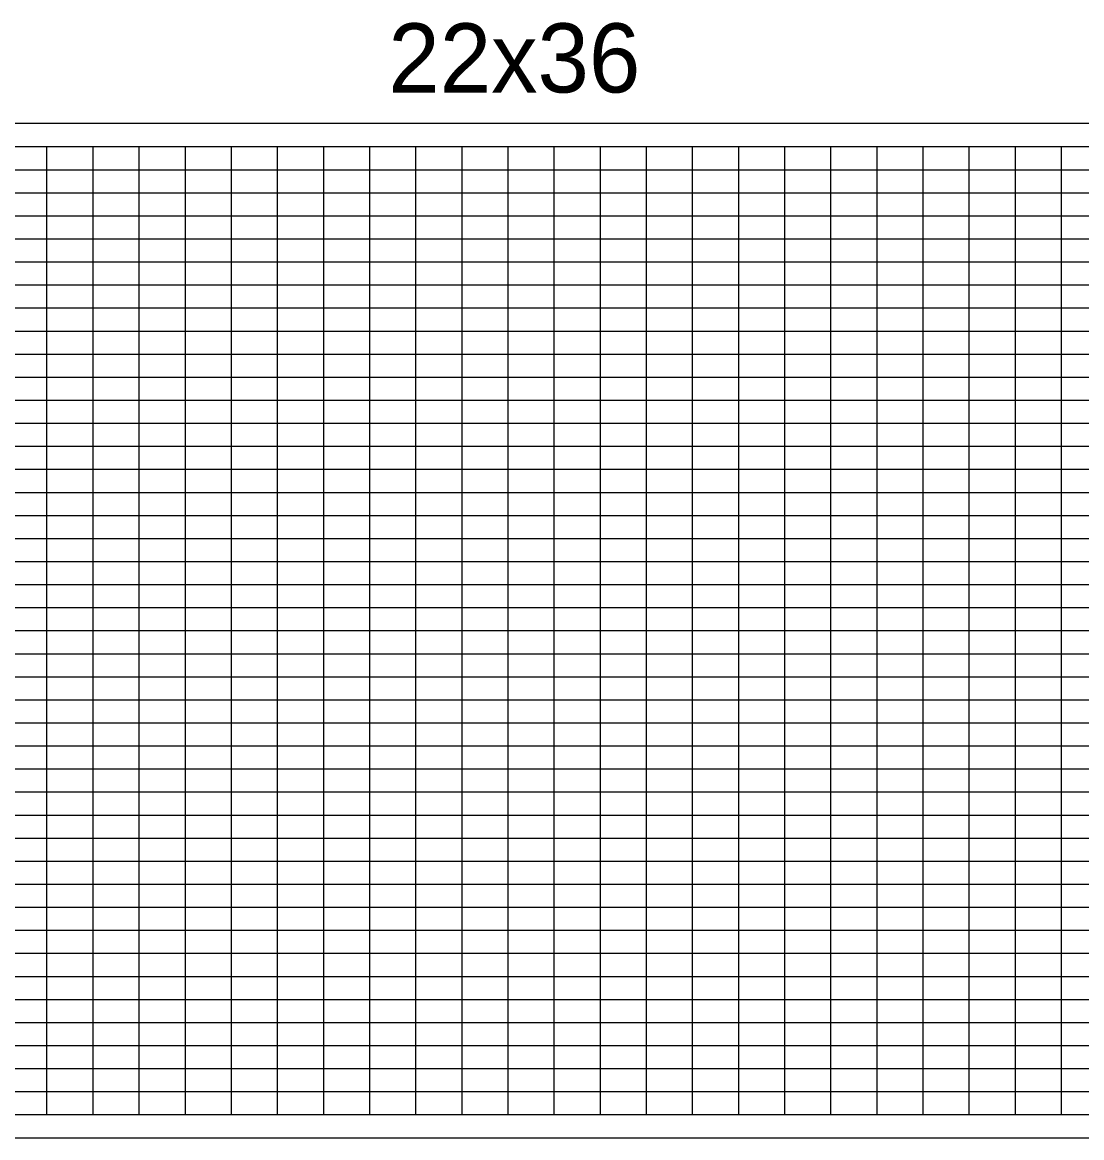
# Model space of a CAD drawing. Extents: x 1873632 to 1926512, y 813126 to 836257.
# Drawn here: x 1895536 to 1896685, y 826908 to 828118 of the extents above; entities that cross this region are included whole.
import ezdxf

# ---------------------------------------------------------------- set-up
doc = ezdxf.new("R2010")
doc.units = 0
doc.layers.add('RD_PD_WallFill', color=7, linetype='Continuous')
doc.layers.add('RD_SHT_IplotShp', color=7, linetype='Continuous')

msp = doc.modelspace()

# ---------------------------------------------------------------- linework, layer by layer
at = {"layer": 'RD_PD_WallFill'}
for p, q in [((1894363.1, 827983.1), (1899713.1, 827983.1)), ((1894363.1, 827983.1), (1896113.1, 827983.1)), ((1895563.1, 826933.1), (1895563.1, 827983.1)), ((1895563.1, 826933.1), (1895563.1, 827983.1)), ((1895613.1, 826933.1), (1895613.1, 827983.1)), ((1895613.1, 826933.1), (1895613.1, 827983.1)), ((1895663.1, 826933.1), (1895663.1, 827983.1)), ((1895663.1, 826933.1), (1895663.1, 827983.1)), ((1895713.1, 826933.1), (1895713.1, 827983.1)), ((1895713.1, 826933.1), (1895713.1, 827983.1)), ((1895763.1, 826933.1), (1895763.1, 827983.1)), ((1895763.1, 826933.1), (1895763.1, 827983.1)), ((1895813.1, 826933.1), (1895813.1, 827983.1)), ((1895813.1, 826933.1), (1895813.1, 827983.1)), ((1895863.1, 826933.1), (1895863.1, 827983.1)), ((1895863.1, 826933.1), (1895863.1, 827983.1)), ((1895913.1, 826933.1), (1895913.1, 827983.1)), ((1895913.1, 826933.1), (1895913.1, 827983.1)), ((1895963.1, 826933.1), (1895963.1, 827983.1)), ((1895963.1, 826933.1), (1895963.1, 827983.1)), ((1896013.1, 826933.1), (1896013.1, 827983.1)), ((1896013.1, 826933.1), (1896013.1, 827983.1)), ((1896063.1, 826933.1), (1896063.1, 827983.1)), ((1896063.1, 826933.1), (1896063.1, 827983.1)), ((1896113.1, 826933.1), (1896113.1, 827983.1)), ((1896113.1, 826933.1), (1896113.1, 827983.1)), ((1896163.1, 826933.1), (1896163.1, 827983.1)), ((1896163.1, 826933.1), (1896163.1, 827983.1)), ((1896213.1, 826933.1), (1896213.1, 827983.1)), ((1896213.1, 826933.1), (1896213.1, 827983.1)), ((1896263.1, 826933.1), (1896263.1, 827983.1)), ((1896263.1, 826933.1), (1896263.1, 827983.1)), ((1896313.1, 826933.1), (1896313.1, 827983.1)), ((1896313.1, 826933.1), (1896313.1, 827983.1)), ((1896363.1, 826933.1), (1896363.1, 827983.1)), ((1896363.1, 826933.1), (1896363.1, 827983.1)), ((1896413.1, 826933.1), (1896413.1, 827983.1)), ((1896413.1, 826933.1), (1896413.1, 827983.1)), ((1896463.1, 826933.1), (1896463.1, 827983.1)), ((1896463.1, 826933.1), (1896463.1, 827983.1)), ((1896513.1, 826933.1), (1896513.1, 827983.1)), ((1896513.1, 826933.1), (1896513.1, 827983.1)), ((1896563.1, 826933.1), (1896563.1, 827983.1)), ((1896563.1, 826933.1), (1896563.1, 827983.1)), ((1896613.1, 826933.1), (1896613.1, 827983.1)), ((1896613.1, 826933.1), (1896613.1, 827983.1)), ((1896663.1, 826933.1), (1896663.1, 827983.1)), ((1896663.1, 826933.1), (1896663.1, 827983.1)), ((1894813.1, 827958.1), (1899713.1, 827958.1)), ((1894813.1, 827958.1), (1899713.1, 827958.1)), ((1894813.1, 827933.1), (1899713.1, 827933.1)), ((1894813.1, 827908.1), (1899713.1, 827908.1)), ((1894813.1, 827883.1), (1899713.1, 827883.1)), ((1894813.1, 827858.1), (1899713.1, 827858.1)), ((1894363.1, 827833.1), (1899713.1, 827833.1)), ((1894363.1, 827808.1), (1899713.1, 827808.1)), ((1894363.1, 827783.1), (1899713.1, 827783.1)), ((1894363.1, 827758.1), (1899713.1, 827758.1)), ((1894363.1, 827733.1), (1899713.1, 827733.1)), ((1894363.1, 827708.1), (1899713.1, 827708.1)), ((1894363.1, 827683.1), (1899713.1, 827683.1)), ((1894363.1, 827658.1), (1899713.1, 827658.1)), ((1894363.1, 827633.1), (1899713.1, 827633.1)), ((1894363.1, 827608.1), (1899713.1, 827608.1)), ((1894363.1, 827583.1), (1899713.1, 827583.1)), ((1894363.1, 827558.1), (1899713.1, 827558.1)), ((1894363.1, 827533.1), (1899713.1, 827533.1)), ((1894363.1, 827508.1), (1899713.1, 827508.1)), ((1894363.1, 827483.1), (1899713.1, 827483.1)), ((1894363.1, 827458.1), (1899713.1, 827458.1)), ((1894363.1, 827433.1), (1899713.1, 827433.1)), ((1894363.1, 827408.1), (1899713.1, 827408.1)), ((1894363.1, 827383.1), (1899713.1, 827383.1)), ((1894363.1, 827358.1), (1899713.1, 827358.1)), ((1894363.1, 827333.1), (1899713.1, 827333.1)), ((1894363.1, 827308.1), (1899713.1, 827308.1)), ((1894363.1, 827283.1), (1899713.1, 827283.1)), ((1894363.1, 827258.1), (1899713.1, 827258.1)), ((1894363.1, 827233.1), (1899713.1, 827233.1)), ((1894363.1, 827208.1), (1899713.1, 827208.1)), ((1894363.1, 827183.1), (1899713.1, 827183.1)), ((1894363.1, 827158.1), (1899713.1, 827158.1)), ((1894363.1, 827133.1), (1899713.1, 827133.1)), ((1894363.1, 827108.1), (1899713.1, 827108.1)), ((1894363.1, 827083.1), (1899713.1, 827083.1)), ((1894363.1, 827058.1), (1899713.1, 827058.1)), ((1894363.1, 827033.1), (1899713.1, 827033.1)), ((1894363.1, 827008.1), (1899713.1, 827008.1)), ((1894363.1, 826983.1), (1899713.1, 826983.1)), ((1894363.1, 826958.1), (1899713.1, 826958.1)), ((1894363.1, 826933.1), (1899713.1, 826933.1)), ((1894363.1, 826933.1), (1899713.1, 826933.1))]:
    msp.add_line(p, q, dxfattribs=at)
at = {"layer": 'RD_SHT_IplotShp'}
msp.add_lwpolyline([(1894338.1, 826908.1), (1899738.1, 826908.1), (1899738.1, 828008.1), (1894338.1, 828008.1)], close=True, dxfattribs=at)

# ---------------------------------------------------------------- texts
at = {"layer": 'RD_PD_WallFill'}
msp.add_text('22x36', height=75, dxfattribs=at).set_placement((1895933.2, 828041.8))
msp.add_text('22x36', height=75, dxfattribs=at).set_placement((1895933.2, 828041.8))

doc.saveas('drawing.dxf')
